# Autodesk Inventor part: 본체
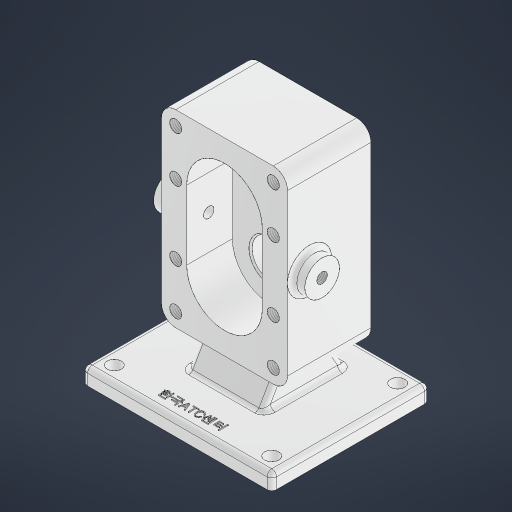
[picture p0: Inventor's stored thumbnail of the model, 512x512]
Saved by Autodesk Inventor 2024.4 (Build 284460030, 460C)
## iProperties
Created: 2026-10
Part Number: 본체
Material: 알루미늄 6061
Document SubType Name: Modeling
Designer: user
Density: 2.7 g/cm^3
Appearance: 알루미늄 - 평지
Mass: 1476.64 g
Surface Area: 830.225 cm^2
Volume: 546.904 cm^3
Author: user
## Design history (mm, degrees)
sketch "스케치1"
  geometry: L1 (-40, -26.5)-(40, -26.5); L2 (40, -26.5)-(40, 26.5); L3 (40, 26.5)-(-40, 26.5); L4 (-40, 26.5)-(-40, -26.5); L5 (-40, -26.5)-(40, 26.5); L6 (40, -26.5)-(-40, 26.5); 1 further point
  constraints: 12 end point, 2 midpoint, 2 parallel, 1 horizontal, 1 perpendicular
  dimensions: "d2" = 80 distance of L3.end L2.end; "d3" = 53 distance of L2.end L1.end
extrude "돌출1" new body sketch "스케치1" stored distance "d4" = 120; taper "d5" = 0 deg
fillet "모깎기1" dims "d6" = 9
sketch "스케치2"
  geometry: L1 (31, 38)-(31, 82); L2 (7, 38)-(7, 82); L3 (55, 82)-(55, 38); A1 r 24 centre (31, 38) between (7, 38) and (55, 38); A2 r 24 centre (31, 82) between (55, 82) and (7, 82); 3 further points
  constraints: 8 end point, 6 point on circle, 4 tangent, 2 centre point, 1 midpoint, 1 parallel, 1 vertical
  dimensions: "d7" = 48 distance between parallel lines of L2 L3; "d8" = 92 distance of point (31, 14) point (31, 106)
extrude "돌출2" cut sketch "스케치2" distance "d9" = 29; taper "d10" = 0 deg
sketch "스케치3"
  geometry: C1 r 12.5 at (31, 82); C2 r 12.5 at (31, 38); A1 r 24 centre (31, 38) between (7, 38) and (55, 38) reference; A2 r 24 centre (31, 82) between (55, 82) and (7, 82) reference; 1 further point
  constraints: 2 centre point, 2 coincident
  dimensions: "d11" = 25 diameter of C1; "d12" = 25 diameter of C2
extrude "돌출3" cut sketch "스케치3" distance "d13" = 15; taper "d14" = 0 deg
sketch "스케치4"
  geometry: C1 r 12.5 at (31, 38) reference; C2 r 19 at (31, 38); 1 further point
  constraints: 1 centre point, 1 coincident
  dimensions: "d15" = 38 diameter of C2
extrude "돌출4" join sketch "스케치4" distance "d16" = 17; taper "d17" = 0 deg
sketch "스케치5"
  geometry: C1 r 19 at (0, 0) reference; C2 r 14 at (0, 0); 1 further point
  constraints: 1 centre point, 1 coincident
  dimensions: "d18" = 28 diameter of C2
extrude "돌출5" cut sketch "스케치5" distance "d19" = 7.3; taper "d20" = 0 deg
sketch "스케치6"
  geometry: C1 r 12.5 at (0, 0) reference; C2 r 8.5 at (0, 0); 1 further point
  constraints: 1 centre point, 1 coincident
  dimensions: "d21" = 17 diameter of C2
extrude "돌출6" cut sketch "스케치6" distance "d22" = 29; taper "d23" = 0 deg
node "작업 평면1"
sketch "스케치9"
  geometry: L1 (19, 43.5)-(-19, 43.5) reference; L2 (60, -56.5)-(-60, -56.5); L3 (-60, -56.5)-(-60, 43.5); L4 (-60, 43.5)-(60, 43.5); L5 (60, 43.5)-(60, -56.5); L6 (60, -56.5)-(-60, 43.5); L7 (-60, -56.5)-(60, 43.5); 5 further points
  constraints: 12 end point, 4 midpoint, 2 parallel, 1 horizontal, 1 perpendicular, 1 vertical alignment
  dimensions: "d28" = 120 distance of L3.end L4.end; "d29" = 100 distance of L2.end L3.end
extrude "돌출7" join sketch "스케치9" distance "d30" = 10; taper "d31" = 0 deg
sketch "스케치10"
  geometry: L1 (-26.5, -60)-(26.5, -60) reference; L2 (-56.5, -80)-(43.5, -80) reference; L3 (43.5, -80)-(-56.5, -80) reference; L4 (-14.953, -60)-(-26.5, -80); L5 (14.953, -60)-(26.5, -80); L6 (43.5, -90)-(43.5, -80) reference; 3 further points
  constraints: 4 end point, 4 point on line
  dimensions: "d32" = 60 deg angle of L2 L4; "d33" = 60 deg angle of L2 L5; "d34" = 53 distance of L5.end L4.end; "d35" = 17 distance from line of L6 L5.end
extrude "돌출8" join sketch "스케치10" stored distance "d36" = 48; taper "d37" = 0 deg
sketch "스케치11"
  geometry: L1 (-102, 0)-(0, 0) reference; C1 r 11 at (-51, 14); 1 further point
  constraints: 1 centre point, 1 vertical alignment
  dimensions: "d39" = 22 diameter of C1; "d40" = 14 distance from line of L1 C1.centre
extrude "돌출9" join sketch "스케치11" distance "d41" = 8; taper "d42" = 0 deg
sketch "스케치12"
  geometry: L1 (60, -56.5)-(60, 43.5) reference; L2 (60, 43.5)-(-60, 43.5) reference; C1 r 4.5 at (-50, 33.5); C2 r 4.5 at (50, 33.5); C3 r 4.5 at (-50, -46.5); C4 r 4.5 at (50, -46.5); 1 further point
  constraints: 4 centre point, 2 horizontal alignment, 2 vertical alignment
  dimensions: "d43" = 9 diameter of C1; "d44" = 9 diameter of C2; "d45" = 9 diameter of C3; "d46" = 9 diameter of C4; "d47" = 100 distance of C2.centre C1.centre; "d48" = 10 distance from line of L1 C2.centre; "d49" = 80 distance of C4.centre C2.centre; "d50" = 10 distance from line of L2 C2.centre
fillet "모깎기2" dims "d51" = 3
fillet "모깎기3" dims "d52" = 3
hole "구멍1" sketch "스케치12" diameter "d53" = 9; stored, may be unused: countersink angle "d57" = 90 deg, drill point angle "d59" = 118 deg; dims "d54" = 6, "d55" = 10, "d56" = 5.5, "d58" = 8
sketch "스케치13"
  geometry: A1 r 9 centre (0, 9) between (-9, 9) and (0, 0) reference; A2 r 9 centre (62, 9) between (62, 0) and (71, 9) reference; A3 r 9 centre (62, 111) between (71, 111) and (62, 120) reference; 9 further points
  constraints: 4 vertical alignment, 3 coincident, 3 horizontal alignment
  dimensions: "d60" = 62 distance of point (62, 111) point (0, 111); "d61" = 29 distance of point (62, 82) point (62, 111); "d63" = 29 distance of point (62, 9) point (62, 38)
hole "구멍2" sketch "스케치13" at (0, 111), (62, 111), (62, 82), (0, 82), (0, 38), (62, 38), (62, 9), (0, 9) diameter "d64" = 7.64684; stored, may be unused: countersink angle "d68" = 90 deg, drill point angle "d70" = 118 deg; dims "d65" = 18, "d66" = 5, "d67" = 2, "d69" = 24.2
sketch "스케치14"
  geometry: L1 (-57, -56.5)-(57, -56.5) reference; 2 further points
  constraints: 1 vertical alignment, 1 other
  dimensions: "d71" = 10 distance from line of point (0, -46.5) L1
sketch "스케치16"
  geometry: C1 r 11 at (0, 0) reference; 2 further points
  constraints: 1 coincident
hole "구멍3" sketch "스케치16" at (0, 0) diameter "d72" = 6.647; stored, may be unused: countersink angle "d76" = 90 deg, drill point angle "d78" = 0 deg; dims "d73" = 8, "d74" = 4, "d75" = 2, "d77" = 24
chamfer "모따기1" distance "d79" = 1; stored, may be unused: second distance "d80" = 2, angle "d81" = 45 deg
fillet "모깎기4" dims "d82" = 0.5
chamfer "모따기2" distance "d83" = 0.7; stored, may be unused: second distance "d84" = 2, angle "d85" = 30 deg
feature "엠보싱1" dims "d2" = 80, "d3" = 53, "d86" = 0.5, "d87" = 0
fillet "모깎기5" dims "d88" = 3
fillet "모깎기6" dims "d89" = 3
sketch "스케치17"
  geometry: C1 r 11 at (0, 0) reference; 2 further points
  constraints: 1 coincident
hole "구멍4" sketch "스케치17" at (0, 0) diameter "d90" = 6.647; stored, may be unused: countersink angle "d94" = 90 deg, drill point angle "d96" = 0 deg; dims "d91" = 8, "d92" = 4, "d93" = 2, "d95" = 24
node "솔리드1"
mirror "미러1"
node "투영된 루프1"
node "투영된 루프2"
